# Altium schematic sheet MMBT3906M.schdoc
size 127 x 101 mm
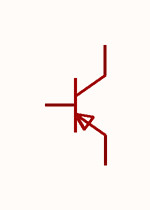
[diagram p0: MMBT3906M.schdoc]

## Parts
Q?  mmbt3906m_c2910283  [SOT-723_L1.2-W0.8-P0.40-LS1.2-BR]  (value not drawn)

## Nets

Not connected (* = marked no-connect by the designer): Q? 1 2 3

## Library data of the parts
Q? = mmbt3906m_c2910283: 晶体管类型:PNP;集电极电流(Ic):200mA;集射极击穿电压(Vceo):40V;耗散功率(Pd):100mW;直流电流增益(hFE):100;; Manufacturer: CJ(江苏长电/长晶); AddInBom: yes; ModelId: abccde1e67074d7481274a37cf5c97f0; ModelName: SOT-723-3P_L1.2-W0.8-H0.6-LS1.2-P0.40; ModelTransform: 47.244,47.244,0,180,0,0,0,0,0; type: PNP; Current - Collector(Ic): 200mA; Collector - Emitter Voltage VCEO: 40V; Pd - Power Dissipation: 100mW; DC Current Gain: 100; Transition frequency(fT): 300MHz; Current - Collector Cutoff: 100nA; Vce Saturation(VCE(sat)): 300mV; Emitter-Base Voltage(Vebo): 5V; Number: 1个PNP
